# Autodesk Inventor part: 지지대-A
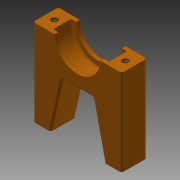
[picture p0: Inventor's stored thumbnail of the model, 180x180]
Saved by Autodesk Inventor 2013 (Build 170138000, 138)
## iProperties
Created: 2018-01
Part Number: 지지대-A
Material: 알루미늄 6061
Document SubType Name: Modeling
Designer: mduedu
Density: 2.71 g/cm^3
Mass: 18.1629 g
Surface Area: 35.102 cm^2
Volume: 6.70218 cm^3
Author: mduedu
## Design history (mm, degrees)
sketch "스케치1"
  geometry: L1 (-17.5, 0)-(17.5, 0); L2 (17.5, 0)-(17.5, 34); L3 (17.5, 34)-(-17.5, 34); L4 (-17.5, 34)-(-17.5, 0); 3 further points
  constraints: 8 end point, 2 midpoint, 1 coincident, 1 horizontal, 1 parallel, 1 vertical, 1 vertical alignment
  dimensions: "d3" = 35 distance of L2.end L3.end; "d4" = 34 distance of L1.end L2.end
extrude "돌출1" new body sketch "스케치1" stored distance "d5" = 10; taper "d6" = 0 deg
sketch "스케치2"
  geometry: L1 (-10.5, 0)-(10.5, 0); L2 (10.5, 0)-(6, 20); L3 (6, 20)-(-6, 20); L4 (-6, 20)-(-10.5, 0); L5 (-17.5, 0)-(17.5, 0) reference; 4 further points
  constraints: 8 end point, 4 midpoint, 1 horizontal, 1 parallel, 1 vertical alignment
  dimensions: "d10" = 20 distance between parallel lines of L1 L3; "d38" = 12 distance of L3.end L2.end; "d39" = 7 distance of L1.start L5.start
extrude "돌출2" cut sketch "스케치2" stored distance "d11" = 10; taper "d12" = 0 deg
sketch "스케치3"
  geometry: L1 (-17.5, 34)-(17.5, 34) reference; C1 r 11 at (0, 34); C2 r 9 at (0, 34); 1 further point
  constraints: 2 centre point, 1 coincident, 1 midpoint
  dimensions: "d13" = 22 diameter of C1; "d16" = 18 diameter of C2
extrude "돌출3" cut sketch "스케치3" stored distance "d14" = 7; taper "d15" = 0 deg
extrude "돌출4" cut sketch "스케치3" stored distance "d17" = 7; taper "d18" = 0 deg
fillet "모깎기1" dims "d19" = 0.3
fillet "모깎기2" dims "d20" = 1
fillet "모깎기3" dims "d21" = 1
fillet "모깎기4" dims "d22" = 1
sketch "스케치4"
  geometry: L1 (-26.5, -7.5)-(-26.5, 0.5) reference; L2 (8.5, 0.5)-(8.5, -7.5) reference; L3 (-20.525, 1.5)-(-25.5, 1.5) reference; 2 further points
  constraints: 1 horizontal alignment
  dimensions: "d43" = 3.5 distance from line of point (-23, -3.5) L1; "d45" = 28 distance of point (5, -3.5) point (-23, -3.5); "d46" = 5 distance from line of L3 point (-23, -3.5)
hole "구멍1" sketch "스케치4" at (-23, -3.5), (5, -3.5) diameter "d23" = 2.459; stored, may be unused: countersink angle "d27" = 90 deg, drill point angle "d29" = 120 deg; dims "d24" = 4.5, "d25" = 4, "d26" = 2, "d28" = 6
sketch "스케치5"
  geometry: L1 (1, 9)-(5.975, 9) reference; L2 (0, 8)-(0, 0) reference; L3 (35, 0)-(35, 8) reference; 4 further points
  constraints: 1 horizontal alignment, 1 other
  dimensions: "d40" = 5 distance from line of L1 point (3.5, 4); "d41" = 3.5 distance from line of L2 point (3.5, 4); "d42" = 3.5 distance from line of L3 point (31.5, 4)
hole "구멍2" sketch "스케치5" diameter "d30" = 2.459; stored, may be unused: countersink angle "d34" = 90 deg, drill point angle "d36" = 120 deg; dims "d31" = 6, "d32" = 4, "d33" = 2, "d35" = 8
node "솔리드1"
